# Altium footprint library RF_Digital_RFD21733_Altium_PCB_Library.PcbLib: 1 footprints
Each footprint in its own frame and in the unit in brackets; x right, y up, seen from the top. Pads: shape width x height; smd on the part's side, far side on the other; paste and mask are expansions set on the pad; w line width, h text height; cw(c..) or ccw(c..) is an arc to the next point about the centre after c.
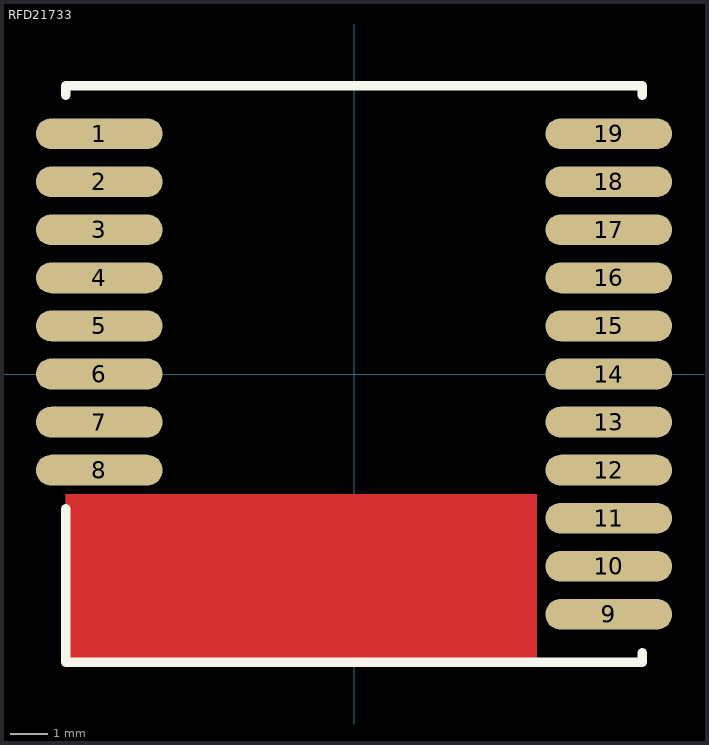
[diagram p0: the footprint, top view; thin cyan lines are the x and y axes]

## RFD21733 [mil] "2.4 GHz RF Transceiver Module"
height 117
pads (19):
  oval 132x32 smd: 1(-265,250) 2(-265,200) 3(-265,150) 4(-265,100) 5(-265,50) 6(-265,0) 7(-265,-50) 8(-265,-100) 9(265,-250) 10(265,-200) 11(265,-150) 12(265,-100) 13(265,-50) 14(265,0) 15(265,50) 16(265,100) 17(265,150) 18(265,200) 19(265,250)
Top Layer:
  pour cut-out: -300,-125 190,-125 190,-300 -300,-300
Bottom Layer:
  pour cut-out: -300,-125 190,-125 190,-300 -300,-300
Top Overlay:
  lines w10: -300,-140 -300,-300 300,-300 300,-290 ; -300,290 -300,300 300,300 300,290
3D body: height 119.29, standoff 0, extent -300,-300 300,300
